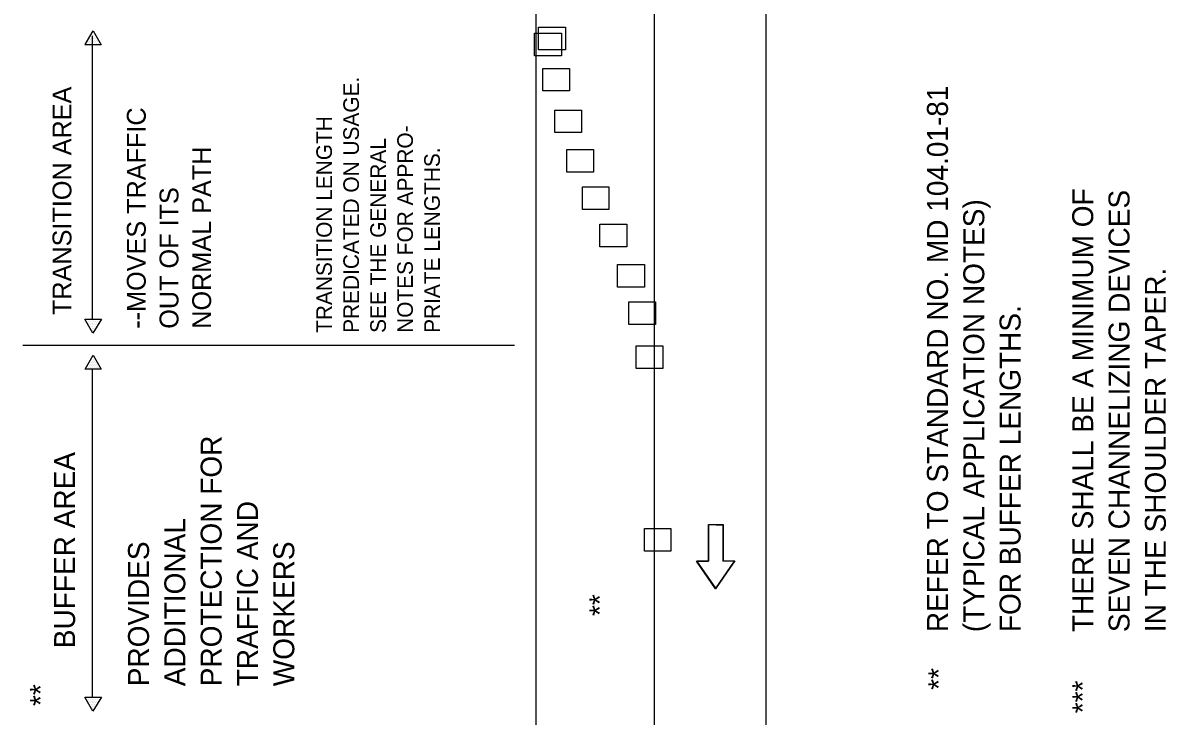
# Model space of a CAD drawing. Extents: x 610.92 to 617.75, y 610.91 to 620.34.
# Drawn here: x 614.338 to 617.612, y 616.047 to 618.032 of the extents above; entities that cross this region are included whole.
import ezdxf

# ---------------------------------------------------------------- set-up
doc = ezdxf.new("R2010")
doc.units = 0
for name, color, linetype in [('DETL-DIMS', 7, 'Continuous'), ('DETL-LINE', 7, 'Continuous'), ('DETL-NOTE', 7, 'Continuous'), ('USER-BORD', 7, 'Continuous')]:
    doc.layers.add(name, color=color, linetype=linetype)

# ---------------------------------------------------------------- blocks, each defined once
blk = doc.blocks.new('DIR4')
at = {"layer": 'USER-BORD'}
for p, q in [((0, 0.0001), (-0.0034, -0.0048)), ((0, 0.0001), (0.0034, -0.0048)), ((-0.0034, -0.0048), (-0.0013, -0.0048)), ((-0.0013, -0.0113), (-0.0013, -0.0048)), ((0.0034, -0.0048), (0.0013, -0.0048)), ((0.0013, -0.0113), (0.0013, -0.0048)), ((-0.0001, -0.0113), (-0.0013, -0.0113)), ((-0.0001, -0.0113), (0.0001, -0.0113)), ((0.0001, -0.0113), (0.0013, -0.0113))]:
    blk.add_line(p, q, dxfattribs=at)

msp = doc.modelspace()

# ---------------------------------------------------------------- linework, layer by layer
at = {"layer": 'DETL-DIMS'}
for p, q in [((614.5166, 617.9692), (614.5398, 618.0092)), ((614.5398, 618.0092), (614.5622, 617.9684)), ((614.5214, 617.9748), (614.5214, 617.9748)), ((614.5238, 617.9788), (614.5238, 617.9788)), ((614.5262, 617.9836), (614.5262, 617.9836)), ((614.527, 617.974), (614.527, 617.974)), ((614.5286, 617.9876), (614.5286, 617.9876)), ((614.5302, 617.9788), (614.5302, 617.9788)), ((614.531, 617.9924), (614.531, 617.9924)), ((614.5326, 617.9828), (614.5326, 617.9828)), ((614.5326, 617.974), (614.5326, 617.974)), ((614.5342, 617.9964), (614.5342, 617.9964)), ((614.535, 617.9868), (614.535, 617.9868)), ((614.5358, 617.9788), (614.5358, 617.9788)), ((614.5366, 618.0012), (614.5366, 618.0012)), ((614.5374, 617.1828), (614.5374, 617.9948)), ((614.5374, 617.9916), (614.5374, 617.9916)), ((614.5382, 617.9828), (614.5382, 617.9828)), ((614.5382, 617.974), (614.5382, 617.974)), ((614.539, 618.0052), (614.539, 618.0052)), ((614.5406, 617.9964), (614.5406, 617.9964)), ((614.5406, 617.9868), (614.5406, 617.9868)), ((614.5406, 617.978), (614.5406, 617.978)), ((614.543, 618.0004), (614.543, 618.0004)), ((614.543, 617.9908), (614.543, 617.9908)), ((614.543, 617.982), (614.543, 617.982)), ((614.5438, 617.974), (614.5438, 617.974)), ((614.5454, 617.9956), (614.5454, 617.9956)), ((614.5454, 617.986), (614.5454, 617.986)), ((614.5462, 617.978), (614.5462, 617.978)), ((614.5486, 617.9908), (614.5486, 617.9908)), ((614.5486, 617.982), (614.5486, 617.982)), ((614.5494, 617.9732), (614.5494, 617.9732)), ((614.551, 617.986), (614.551, 617.986)), ((614.5518, 617.9772), (614.5518, 617.9772)), ((614.555, 617.9812), (614.555, 617.9812)), ((614.5622, 617.9684), (614.5158, 617.9684)), ((614.5158, 617.9684), (614.5158, 617.9684)), ((614.519, 617.9708), (614.519, 617.9708)), ((614.5246, 617.97), (614.5246, 617.97)), ((614.5302, 617.9692), (614.5302, 617.9692)), ((614.5358, 617.9692), (614.5358, 617.9692)), ((614.5414, 617.9692), (614.5414, 617.9692)), ((614.547, 617.9684), (614.547, 617.9684)), ((614.555, 617.9724), (614.555, 617.9724)), ((614.5158, 617.1828), (614.5158, 617.1828)), ((614.539, 617.1436), (614.5158, 617.1828)), ((614.5166, 617.1828), (614.563, 617.1828)), ((614.519, 617.182), (614.519, 617.182)), ((614.5214, 617.1764), (614.5214, 617.1764)), ((614.5238, 617.182), (614.5238, 617.182)), ((614.5238, 617.1716), (614.5238, 617.1716)), ((614.5262, 617.1764), (614.5262, 617.1764)), ((614.5262, 617.1668), (614.5262, 617.1668)), ((614.5286, 617.182), (614.5286, 617.182)), ((614.5286, 617.1716), (614.5286, 617.1716)), ((614.5294, 617.162), (614.5294, 617.162)), ((614.5318, 617.1764), (614.5318, 617.1764)), ((614.5318, 617.1668), (614.5318, 617.1668)), ((614.5318, 617.1564), (614.5318, 617.1564)), ((614.5342, 617.182), (614.5342, 617.182)), ((614.5342, 617.1716), (614.5342, 617.1716)), ((614.5342, 617.162), (614.5342, 617.162)), ((614.5366, 617.1764), (614.5366, 617.1764)), ((614.5366, 617.1668), (614.5366, 617.1668)), ((614.5366, 617.1564), (614.5366, 617.1564)), ((614.563, 617.1828), (614.539, 617.1436)), ((614.539, 617.182), (614.539, 617.182)), ((614.539, 617.1716), (614.539, 617.1716)), ((614.539, 617.162), (614.539, 617.162)), ((614.5414, 617.1764), (614.5414, 617.1764)), ((614.5414, 617.1668), (614.5414, 617.1668)), ((614.5414, 617.1564), (614.5414, 617.1564)), ((614.5438, 617.182), (614.5438, 617.182)), ((614.5438, 617.1716), (614.5438, 617.1716)), ((614.5438, 617.162), (614.5438, 617.162)), ((614.5462, 617.1764), (614.5462, 617.1764)), ((614.5462, 617.1668), (614.5462, 617.1668)), ((614.5462, 617.1564), (614.5462, 617.1564)), ((614.5486, 617.182), (614.5486, 617.182)), ((614.5486, 617.1716), (614.5486, 617.1716)), ((614.5486, 617.162), (614.5486, 617.162)), ((614.5518, 617.1764), (614.5518, 617.1764)), ((614.5518, 617.1668), (614.5518, 617.1668)), ((614.5542, 617.182), (614.5542, 617.182)), ((614.5542, 617.1716), (614.5542, 617.1716)), ((614.5566, 617.1764), (614.5566, 617.1764)), ((614.559, 617.182), (614.559, 617.182)), ((614.539, 617.1516), (614.539, 617.1516)), ((614.3382, 617.1092), (615.7462, 617.1092)), ((614.3382, 617.1092), (615.7462, 617.1092)), ((614.5166, 617.0404), (614.5398, 617.0804)), ((614.5286, 617.0596), (614.5286, 617.0596)), ((614.531, 617.0636), (614.531, 617.0636)), ((614.5342, 617.0676), (614.5342, 617.0676)), ((614.535, 617.0588), (614.535, 617.0588)), ((614.5366, 617.0724), (614.5366, 617.0724)), ((614.5374, 617.0628), (614.5374, 617.0628)), ((614.539, 617.0764), (614.539, 617.0764)), ((614.5398, 617.0804), (614.5622, 617.0396)), ((614.5406, 617.0676), (614.5406, 617.0676)), ((614.5406, 617.058), (614.5406, 617.058)), ((614.543, 617.0716), (614.543, 617.0716)), ((614.543, 617.062), (614.543, 617.062)), ((614.5454, 617.0668), (614.5454, 617.0668)), ((614.5454, 617.058), (614.5454, 617.058)), ((614.5486, 617.0628), (614.5486, 617.0628)), ((614.551, 617.0572), (614.551, 617.0572)), ((614.5158, 617.0396), (614.5158, 617.0396)), ((614.5622, 617.0396), (614.5158, 617.0396)), ((614.519, 617.042), (614.519, 617.042)), ((614.5214, 617.046), (614.5214, 617.046)), ((614.5238, 617.05), (614.5238, 617.05)), ((614.5246, 617.0412), (614.5246, 617.0412)), ((614.5262, 617.0548), (614.5262, 617.0548)), ((614.527, 617.0452), (614.527, 617.0452)), ((614.5302, 617.05), (614.5302, 617.05)), ((614.5302, 617.0412), (614.5302, 617.0412)), ((614.5326, 617.054), (614.5326, 617.054)), ((614.5326, 617.0452), (614.5326, 617.0452)), ((614.5358, 617.05), (614.5358, 617.05)), ((614.5358, 617.0404), (614.5358, 617.0404)), ((614.5374, 616.102), (614.5374, 617.0412)), ((614.5382, 617.054), (614.5382, 617.054)), ((614.5382, 617.0452), (614.5382, 617.0452)), ((614.5406, 617.0492), (614.5406, 617.0492)), ((614.5414, 617.0412), (614.5414, 617.0412)), ((614.543, 617.054), (614.543, 617.054)), ((614.5438, 617.0452), (614.5438, 617.0452)), ((614.5462, 617.0492), (614.5462, 617.0492)), ((614.547, 617.0404), (614.547, 617.0404)), ((614.5486, 617.0532), (614.5486, 617.0532)), ((614.5494, 617.0444), (614.5494, 617.0444)), ((614.5518, 617.0484), (614.5518, 617.0484)), ((614.555, 617.0524), (614.555, 617.0524)), ((614.555, 617.0436), (614.555, 617.0436)), ((614.539, 616.0612), (614.5158, 616.1012)), ((614.5158, 616.1012), (614.5158, 616.1012)), ((614.5166, 616.1012), (614.563, 616.1012)), ((614.519, 616.0996), (614.519, 616.0996)), ((614.5214, 616.094), (614.5214, 616.094)), ((614.5238, 616.0996), (614.5238, 616.0996)), ((614.5238, 616.0892), (614.5238, 616.0892)), ((614.5262, 616.094), (614.5262, 616.094)), ((614.5262, 616.0844), (614.5262, 616.0844)), ((614.5286, 616.0996), (614.5286, 616.0996)), ((614.5286, 616.0892), (614.5286, 616.0892)), ((614.5294, 616.0796), (614.5294, 616.0796)), ((614.5318, 616.094), (614.5318, 616.094)), ((614.5318, 616.0844), (614.5318, 616.0844)), ((614.5318, 616.074), (614.5318, 616.074)), ((614.5342, 616.0996), (614.5342, 616.0996)), ((614.5342, 616.0892), (614.5342, 616.0892)), ((614.5342, 616.0796), (614.5342, 616.0796)), ((614.5366, 616.094), (614.5366, 616.094)), ((614.5366, 616.0844), (614.5366, 616.0844)), ((614.5366, 616.074), (614.5366, 616.074)), ((614.563, 616.1012), (614.539, 616.0612)), ((614.539, 616.0996), (614.539, 616.0996)), ((614.539, 616.0892), (614.539, 616.0892)), ((614.539, 616.0796), (614.539, 616.0796)), ((614.5414, 616.094), (614.5414, 616.094)), ((614.5414, 616.0844), (614.5414, 616.0844)), ((614.5414, 616.074), (614.5414, 616.074)), ((614.5438, 616.0996), (614.5438, 616.0996)), ((614.5438, 616.0892), (614.5438, 616.0892)), ((614.5438, 616.0796), (614.5438, 616.0796)), ((614.5462, 616.094), (614.5462, 616.094)), ((614.5462, 616.0844), (614.5462, 616.0844)), ((614.5462, 616.074), (614.5462, 616.074)), ((614.5486, 616.0996), (614.5486, 616.0996)), ((614.5486, 616.0892), (614.5486, 616.0892)), ((614.5486, 616.0796), (614.5486, 616.0796)), ((614.5518, 616.094), (614.5518, 616.094)), ((614.5518, 616.0844), (614.5518, 616.0844)), ((614.5542, 616.0996), (614.5542, 616.0996)), ((614.5542, 616.0892), (614.5542, 616.0892)), ((614.5566, 616.094), (614.5566, 616.094)), ((614.559, 616.0996), (614.559, 616.0996)), ((614.539, 616.0692), (614.539, 616.0692))]:
    msp.add_line(p, q, dxfattribs=at)
at = {"layer": 'DETL-LINE'}
for p, q in [((615.8086, 613.3204), (615.8086, 620.3372)), ((616.147, 613.3204), (616.147, 620.3316)), ((616.467, 613.3204), (616.467, 620.3372))]:
    msp.add_line(p, q, dxfattribs=at)
for points in [[(615.815, 617.954), (615.815, 618.0188), (615.8918, 618.0188), (615.8918, 617.954)], [(615.815, 617.954), (615.815, 618.0188), (615.8918, 618.0188), (615.8918, 617.954)], [(615.815, 617.954), (615.815, 618.0188), (615.8918, 618.0188), (615.8918, 617.954)], [(615.815, 617.954), (615.815, 618.0188), (615.8918, 618.0188), (615.8918, 617.954)], [(615.815, 617.954), (615.815, 618.0188), (615.8918, 618.0188), (615.8918, 617.954)], [(615.815, 617.954), (615.815, 618.0188), (615.8918, 618.0188), (615.8918, 617.954)], [(615.815, 617.954), (615.815, 618.0188), (615.8918, 618.0188), (615.8918, 617.954)], [(615.815, 617.954), (615.815, 618.0188), (615.8918, 618.0188), (615.8918, 617.954)], [(615.815, 617.954), (615.815, 618.0188), (615.8918, 618.0188), (615.8918, 617.954)], [(615.815, 617.954), (615.815, 618.0188), (615.8918, 618.0188), (615.8918, 617.954)], [(615.8038, 617.9372), (615.8038, 618.002), (615.8806, 618.002), (615.8806, 617.9372)], [(615.827, 617.8372), (615.827, 617.9012), (615.9038, 617.9012), (615.9038, 617.8372)], [(615.827, 617.8372), (615.827, 617.9012), (615.9038, 617.9012), (615.9038, 617.8372)], [(615.827, 617.8372), (615.827, 617.9012), (615.9038, 617.9012), (615.9038, 617.8372)], [(615.8614, 617.718), (615.8614, 617.782), (615.9382, 617.782), (615.9382, 617.718)], [(615.8614, 617.718), (615.8614, 617.782), (615.9382, 617.782), (615.9382, 617.718)], [(615.8614, 617.718), (615.8614, 617.782), (615.9382, 617.782), (615.9382, 617.718)], [(615.8614, 617.718), (615.8614, 617.782), (615.9382, 617.782), (615.9382, 617.718)], [(615.8614, 617.718), (615.8614, 617.782), (615.9382, 617.782), (615.9382, 617.718)], [(615.8614, 617.718), (615.8614, 617.782), (615.9382, 617.782), (615.9382, 617.718)], [(615.8614, 617.718), (615.8614, 617.782), (615.9382, 617.782), (615.9382, 617.718)], [(615.8614, 617.718), (615.8614, 617.782), (615.9382, 617.782), (615.9382, 617.718)], [(615.8614, 617.718), (615.8614, 617.782), (615.9382, 617.782), (615.9382, 617.718)], [(615.8614, 617.718), (615.8614, 617.782), (615.9382, 617.782), (615.9382, 617.718)], [(615.8614, 617.718), (615.8614, 617.782), (615.9382, 617.782), (615.9382, 617.718)], [(615.8958, 617.6044), (615.8958, 617.6692), (615.9726, 617.6692), (615.9726, 617.6044)], [(615.8958, 617.6044), (615.8958, 617.6692), (615.9726, 617.6692), (615.9726, 617.6044)], [(615.8958, 617.6044), (615.8958, 617.6692), (615.9726, 617.6692), (615.9726, 617.6044)], [(615.9406, 617.4972), (615.9406, 617.562), (616.0166, 617.562), (616.0166, 617.4972)], [(615.9406, 617.4972), (615.9406, 617.562), (616.0166, 617.562), (616.0166, 617.4972)], [(615.9406, 617.4972), (615.9406, 617.562), (616.0166, 617.562), (616.0166, 617.4972)], [(615.991, 617.39), (615.991, 617.4548), (616.0678, 617.4548), (616.0678, 617.39)], [(615.991, 617.39), (615.991, 617.4548), (616.0678, 617.4548), (616.0678, 617.39)], [(615.991, 617.39), (615.991, 617.4548), (616.0678, 617.4548), (616.0678, 617.39)], [(616.0414, 617.2748), (616.0414, 617.3396), (616.1182, 617.3396), (616.1182, 617.2748)], [(616.0414, 617.2748), (616.0414, 617.3396), (616.1182, 617.3396), (616.1182, 617.2748)], [(616.0414, 617.2748), (616.0414, 617.3396), (616.1182, 617.3396), (616.1182, 617.2748)], [(616.0414, 617.2748), (616.0414, 617.3396), (616.1182, 617.3396), (616.1182, 617.2748)], [(616.0734, 617.1676), (616.0734, 617.2324), (616.1502, 617.2324), (616.1502, 617.1676)], [(616.0734, 617.1676), (616.0734, 617.2324), (616.1502, 617.2324), (616.1502, 617.1676)], [(616.0734, 617.1676), (616.0734, 617.2324), (616.1502, 617.2324), (616.1502, 617.1676)], [(616.0734, 617.1676), (616.0734, 617.2324), (616.1502, 617.2324), (616.1502, 617.1676)], [(616.0734, 617.1676), (616.0734, 617.2324), (616.1502, 617.2324), (616.1502, 617.1676)], [(616.0734, 617.1676), (616.0734, 617.2324), (616.1502, 617.2324), (616.1502, 617.1676)], [(616.0734, 617.1676), (616.0734, 617.2324), (616.1502, 617.2324), (616.1502, 617.1676)], [(616.0734, 617.1676), (616.0734, 617.2324), (616.1502, 617.2324), (616.1502, 617.1676)], [(616.0942, 617.042), (616.0942, 617.1068), (616.171, 617.1068), (616.171, 617.042)], [(616.1182, 616.5188), (616.1182, 616.5836), (616.1942, 616.5836), (616.1942, 616.5188)], [(616.3022, 616.5956), (616.3438, 616.5956), (616.3438, 616.4916), (616.3774, 616.4916), (616.323, 616.4132), (616.2686, 616.4916), (616.3022, 616.4916)]]:
    msp.add_lwpolyline(points, close=True, dxfattribs=at)
for points in [[(616.147, 617.8204), (616.147, 617.9404)], [(616.147, 617.3404), (616.147, 617.4604)], [(616.147, 616.8604), (616.147, 616.9804)], [(616.147, 616.3804), (616.147, 616.5004)]]:
    msp.add_lwpolyline(points, dxfattribs=at)

# ---------------------------------------------------------------- block references
at = {"layer": 'DETL-LINE', "xscale": 16, "yscale": 16, "rotation": 180}
for p in [(616.3221, 616.4132), (616.3229, 616.4132), (616.3229, 616.4132)]:
    msp.add_blockref('DIR4', p, dxfattribs=at)

# ---------------------------------------------------------------- texts
at = {"layer": 'DETL-NOTE'}
for s, height, p in [('TRANSITION AREA', 0.054, (614.4772, 617.195)), ('PREDICATED ON USAGE.', 0.044661, (615.3006, 617.144)), ('REFER TO STANDARD NO. MD 104.01-81', 0.06, (616.9875, 616.2872)), ('--MOVES TRAFFIC', 0.054, (614.6901, 617.1558)), ('TRANSITION LENGTH', 0.044661, (615.2233, 617.144)), ('NOTES FOR APPRO-', 0.044661, (615.4551, 617.144)), ('SEE THE GENERAL', 0.044661, (615.3778, 617.144)), ('NORMAL PATH', 0.054, (614.8773, 617.1558)), ('PRIATE LENGTHS.', 0.044661, (615.5324, 617.144)), ('OUT OF ITS', 0.054, (614.7837, 617.1558)), ('THERE SHALL BE A MINIMUM OF ', 0.06, (617.4035, 616.2872)), ('SEVEN CHANNELIZING DEVICES ', 0.06, (617.5075, 616.2872)), ('(TYPICAL APPLICATION NOTES)', 0.06, (617.0915, 616.2872)), ('IN THE SHOULDER TAPER.', 0.06, (617.6115, 616.2872)), ('FOR BUFFER LENGTHS.', 0.06, (617.1955, 616.2872)), ('PROTECTION FOR', 0.06, (614.9074, 616.1322)), ('BUFFER AREA ', 0.06, (614.4877, 616.2412)), ('TRAFFIC AND', 0.06, (615.0114, 616.1322)), ('ADDITIONAL', 0.06, (614.8034, 616.1322)), ('PROVIDES', 0.06, (614.6994, 616.1322)), ('WORKERS', 0.06, (615.1154, 616.1322)), ('**', 0.06, (616.0205, 616.3332)), ('**', 0.06, (616.9909, 616.122)), ('***', 0.06, (617.4034, 616.0548)), ('**', 0.06, (614.4189, 616.0756))]:
    msp.add_text(s, height=height, rotation=90, dxfattribs=at).set_placement(p)

doc.saveas('drawing.dxf')
